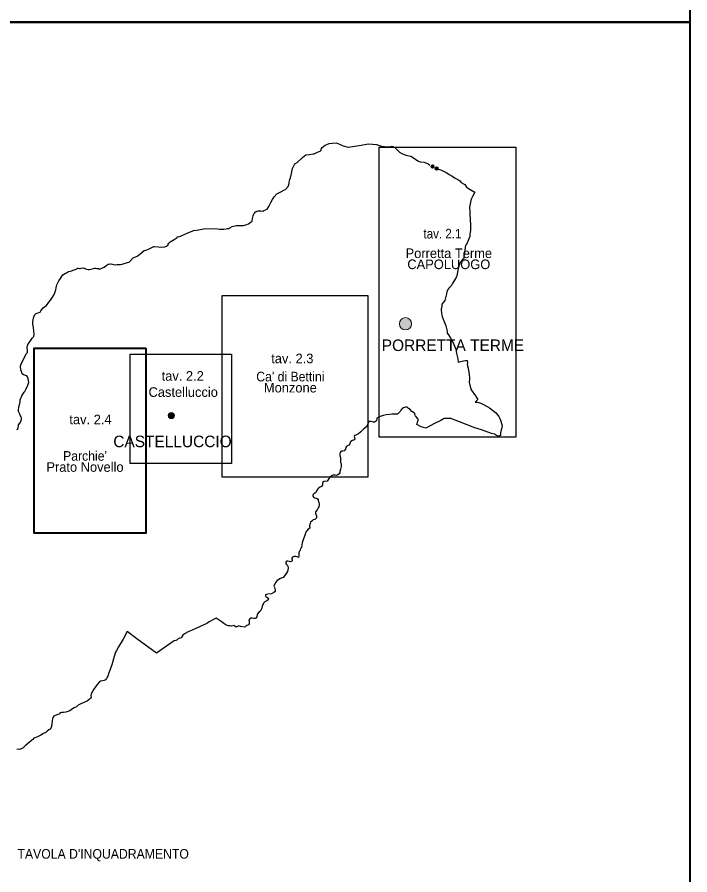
# Model space of a CAD drawing. Extents: x 650071 to 653841, y 889105 to 891996.
# Drawn here: x 650422 to 651121, y 889623 to 890515 of the extents above; entities that cross this region are included whole.
import ezdxf
from ezdxf.enums import TextEntityAlignment as Align

# ---------------------------------------------------------------- set-up
doc = ezdxf.new("R2010")
doc.units = 0
doc.header["$LTSCALE"] = 5.6
doc.header["$PDMODE"] = 32
doc.header["$PDSIZE"] = 2.8
doc.layers.add('61', color=7, linetype='Continuous', lineweight=35)

msp = doc.modelspace()

# ---------------------------------------------------------------- hatches: boundary and pattern name
at = {"layer": '61'}
for points in [[(650832.21, 890195.85, 1), (650819.49, 890195.85, 1)], [(650585.6, 890100.36, 1), (650579.24, 890100.36, 1)]]:
    msp.add_hatch(color=256, dxfattribs=at).paths.add_polyline_path(points)

# ---------------------------------------------------------------- linework, layer by layer
at = {"layer": '61', "lineweight": 40}
for p, q in [((650071.44, 890509.41), (651121.44, 890509.41)), ((651121.44, 890509.41), (651121.44, 889106.05))]:
    msp.add_line(p, q, dxfattribs=at)
for points in [[(651121.44, 891995.65), (651121.44, 890509.4), (650071.44, 890509.4), (650071.44, 891995.65)], [(650555.91, 890170.4), (650555.91, 889977.97), (650439.81, 889977.97), (650439.81, 890170.4)]]:
    msp.add_lwpolyline(points, close=True, dxfattribs=at)
at = {"layer": '61', "lineweight": 25}
for points in [[(650703.73, 890338.52), (650704.95, 890341.6), (650704.71, 890343.23), (650705.73, 890345.71), (650706.25, 890347.72), (650707.39, 890352.16), (650707.99, 890355.64), (650707.99, 890356.68), (650709.37, 890359.23), (650710.85, 890362), (650713.27, 890363.56), (650718.57, 890368.59), (650720.35, 890370.19), (650722.21, 890371.35), (650726.01, 890371.8), (650729.77, 890372.4), (650730.95, 890372.63), (650734.33, 890374.35), (650737.65, 890375.79), (650738.47, 890377.96), (650739.25, 890379.07), (650740.75, 890380.35), (650742.23, 890381.51), (650744.07, 890382.4), (650746.57, 890383.28), (650749.91, 890383.63), (650753.89, 890383.92), (650757.33, 890382.48), (650759.23, 890381.63), (650760.99, 890380.91), (650766.13, 890379.51), (650777.53, 890381.2), (650787.49, 890382.84), (650795.51, 890382.39), (650800.81, 890380.44), (650804.15, 890380.19), (650808.97, 890379.83), (650811.61, 890380.39), (650812.57, 890380.32), (650813.47, 890379.92)], [(650813.47, 890379.92), (650814.37, 890379.31), (650815.69, 890378.07), (650817.93, 890375.96), (650819.65, 890374.27), (650821.93, 890372.79), (650826.13, 890371.08), (650831.53, 890369.96), (650835.13, 890367.55), (650838.67, 890365.39), (650841.13, 890364.24), (650845.39, 890363.95), (650849.47, 890362.04), (650851.11, 890360.87)], [(650858.21, 890357.36), (650863.15, 890355.56), (650866.75, 890353.67), (650868.85, 890352.64), (650871.25, 890351.2), (650874.07, 890349.59), (650876.77, 890347.72), (650880.31, 890345.88), (650882.23, 890344.44), (650883.77, 890342.75), (650886.25, 890341.24), (650887.63, 890340.48), (650888.17, 890339.64), (650889.33, 890337.96), (650889.85, 890337.44), (650891.43, 890336.43), (650897.89, 890332.68), (650895.31, 890328), (650894.47, 890326.15), (650893.77, 890324.04), (650892.49, 890317.08), (650892.55, 890312.08), (650892.87, 890309.64), (650893.03, 890304.52), (650893.19, 890302.64), (650893.41, 890300.23), (650893.39, 890293.12), (650892.97, 890290.71), (650892.81, 890289.47), (650892.75, 890288.07), (650892.55, 890286.31), (650892.39, 890285.79), (650890.81, 890282.28), (650888.73, 890277.6), (650888.31, 890277.52), (650887.57, 890272.24), (650887.27, 890270.67), (650887.07, 890268.39), (650886.63, 890266.15), (650886.31, 890264.16)], [(650605.45, 890292.75), (650608.37, 890293.27), (650618.07, 890294.8), (650630.45, 890294.43), (650632.49, 890294.28), (650636.89, 890294.07), (650639.39, 890294.52), (650640.87, 890294.92), (650642.19, 890294.99), (650643.01, 890295.68), (650645.77, 890296.95), (650648.37, 890297.8), (650649.73, 890298.04), (650652.25, 890298.11), (650655.57, 890298.11), (650657.41, 890298.11), (650660.93, 890299.12), (650662.71, 890299.6), (650664.31, 890301), (650666.29, 890302.48), (650666.65, 890305.24), (650667.31, 890308.2), (650668.25, 890310.04), (650669.05, 890311.11), (650669.71, 890312.32), (650672.61, 890313.36), (650675.47, 890313.12), (650677.55, 890313.07), (650678.69, 890313.64), (650682.13, 890314.96), (650683.63, 890317.75), (650685.77, 890321.79), (650687.37, 890324.95), (650689.39, 890327.79), (650691.89, 890330.84), (650692.67, 890331.4), (650696.11, 890333.04), (650699.27, 890334.72), (650700.93, 890335.47), (650703.73, 890338.52)], [(650507.65, 890252.71), (650510.23, 890253.71), (650512.59, 890254.75), (650514.57, 890256.31), (650516.61, 890257.84), (650517.49, 890257.92), (650519.23, 890258.2), (650519.87, 890258.16), (650523.81, 890257.04), (650524.45, 890257.04), (650526.19, 890257.31), (650529.49, 890257.55), (650531.23, 890257.92), (650533.27, 890258.47), (650536.83, 890259.47), (650538.61, 890260), (650542.81, 890264.23), (650546.71, 890266.2), (650549.77, 890268.36), (650554.03, 890271.96), (650556.85, 890272.84), (650560.03, 890274.19), (650564.29, 890276.04), (650564.99, 890276.08), (650568.81, 890275.92), (650572.07, 890275.36), (650575.51, 890275.67), (650577.49, 890276.59), (650579.15, 890277.96), (650579.09, 890278.44), (650579.85, 890279.56), (650581.01, 890280.99), (650585.21, 890283.4), (650588.29, 890285.56), (650588.51, 890286.11), (650591.23, 890286.47), (650592.73, 890287.24), (650598.97, 890289.96), (650604.63, 890292.47), (650605.45, 890292.75)], [(650886.31, 890264.16), (650886.11, 890263.47), (650885.17, 890262.48), (650884.17, 890261.4), (650883.53, 890260.52), (650882.79, 890259.47), (650881.79, 890257.16), (650881.25, 890255.8), (650880.55, 890252.87), (650879.87, 890249.43), (650879.13, 890245.75), (650878.87, 890244.95), (650878.33, 890244.04), (650876.07, 890240.03), (650874.49, 890237.31), (650873.13, 890235.32), (650871.03, 890232.79), (650870.13, 890231.67), (650869.11, 890230.44), (650868.35, 890227.03), (650867.33, 890222.68), (650866.69, 890220.07), (650865.17, 890218.23), (650863.75, 890216.31), (650863.75, 890215.92), (650863.69, 890214.24), (650863.13, 890212.15), (650862.87, 890211.16), (650862.99, 890210.23), (650863.25, 890206.83), (650863.51, 890204.91), (650864.01, 890203.48), (650864.97, 890200.76), (650866.57, 890196.36), (650867.71, 890193.59), (650869.25, 890188.07), (650869.25, 890187.31), (650868.99, 890186.07), (650870.41, 890184.28), (650872.19, 890181.55)], [(650458.87, 890223.52), (650460.49, 890226.31), (650461.25, 890228.04), (650462.13, 890230.95), (650462.71, 890233.2), (650463.47, 890236.16), (650464.41, 890238.47), (650465.51, 890240.44), (650467.03, 890243.04), (650468.11, 890244.6), (650469.67, 890246.83), (650472.33, 890248.44), (650473.49, 890248.68), (650474.51, 890249.31), (650475.53, 890250.04), (650477.59, 890250.67), (650482.37, 890252.16), (650483.59, 890252.52), (650484.09, 890252.88), (650484.91, 890253.52), (650485.57, 890253.52), (650486.75, 890253.27), (650487.45, 890253.27), (650488.73, 890253.71), (650490.85, 890253.84), (650491.81, 890253.52), (650492.95, 890253.03), (650494.55, 890252.52), (650495.77, 890252.28), (650496.85, 890252.28), (650498.51, 890252.64), (650499.91, 890253.03), (650501.45, 890253.4), (650502.65, 890253.47), (650503.43, 890253.47), (650505.01, 890253.27), (650506.49, 890253.15), (650507.65, 890252.71)], [(650433.67, 890138.67), (650432.65, 890140.47), (650432.03, 890141.52), (650428.83, 890142.75), (650427.31, 890143.6), (650426.65, 890146.28), (650426.03, 890147.95), (650425.69, 890151.28), (650425.95, 890153.28), (650426.35, 890154.15), (650431.77, 890164.8), (650432.73, 890166.04), (650432.77, 890166.87), (650432.65, 890168.11), (650432.33, 890171.03), (650432.91, 890173.2), (650433.49, 890174.92), (650435.21, 890177.2), (650437.69, 890180.68), (650439.29, 890182.6), (650439.67, 890184.96), (650439.43, 890188.36), (650439.17, 890191.84), (650438.47, 890195.36), (650438.39, 890197.48), (650438.77, 890200.08), (650439.49, 890203.12), (650440.51, 890205.55), (650441.01, 890205.99), (650442.43, 890206.72), (650445.03, 890207.52), (650445.85, 890208.03), (650446.81, 890209.2), (650447.89, 890210.8), (650449.11, 890212.43), (650450.65, 890213.48), (650452.43, 890214.91), (650454.85, 890218.12), (650456.59, 890220.36), (650458.87, 890223.52)], [(650872.19, 890181.55), (650875.11, 890176.84), (650876.13, 890174.19), (650877.99, 890169.48), (650879.01, 890164.79), (650880.15, 890159.51), (650880.73, 890155.84), (650881.87, 890156.2), (650886.01, 890157.2), (650888.07, 890157.59), (650889.85, 890157.47), (650890.29, 890155.28), (650890.11, 890154.36), (650889.97, 890153.8), (650890.43, 890152.12), (650890.99, 890149.6), (650891.45, 890147.36), (650891.71, 890145.39), (650891.95, 890142.91), (650892.21, 890139.51), (650892.41, 890138.52), (650892.09, 890134.6), (650892.27, 890133.28), (650892.73, 890132.55), (650892.67, 890131.99), (650894.25, 890127.04), (650898.67, 890120.72), (650900.89, 890117.03), (650898.25, 890114.28), (650899.67, 890114.23), (650900.67, 890114.32), (650902.03, 890114), (650904.07, 890113.31), (650906.33, 890112.28), (650910.67, 890109.87), (650913.27, 890108.24), (650916.41, 890106.08), (650919.33, 890103.48), (650921.31, 890101.16), (650922.97, 890099.24)], [(650421.81, 890085.72), (650422.69, 890086.15), (650422.83, 890086.96), (650423.21, 890087.95), (650423.35, 890089.44), (650423.59, 890090.8), (650424.81, 890092.52), (650426.23, 890094.83), (650426.53, 890096.51), (650426.53, 890097.72), (650426.23, 890099.08), (650425.71, 890100.08), (650424.81, 890101.96), (650423.53, 890104.75), (650423.41, 890105.87), (650423.91, 890109.47), (650424.87, 890112.92), (650425.33, 890114.6), (650425.27, 890116.59), (650426.91, 890120.8), (650428.07, 890122.67), (650429.35, 890124.59), (650430.11, 890125.24), (650431.39, 890128.11), (650433.05, 890132), (650434.27, 890134.68), (650433.67, 890138.67)], [(650822.67, 890108.2), (650820.97, 890105.88), (650820.43, 890104.56), (650819.29, 890103.52), (650817.51, 890101.92), (650816.49, 890101.87), (650813.25, 890101.95), (650812.09, 890101.87), (650809.31, 890101.48), (650805.71, 890101.2), (650802.43, 890100.55), (650799.45, 890099.36), (650796.05, 890097.6), (650795.65, 890094.96), (650793.47, 890093.36), (650792.53, 890093.56), (650790.01, 890094.11), (650787.61, 890094.16), (650786.75, 890091.79), (650785.11, 890088.68), (650782.19, 890086.24), (650779.47, 890083.56), (650776.95, 890081.24), (650774.29, 890080.12), (650772.63, 890079.55), (650772.37, 890078.51), (650772.85, 890077.71), (650773.17, 890076.12), (650772.57, 890075.07), (650770.67, 890074.28), (650768.89, 890073.48), (650768.41, 890072.56), (650768.01, 890070.79), (650766.77, 890069.68), (650765.25, 890068.79), (650764.39, 890068.12), (650763.85, 890067.23), (650763.55, 890065.36), (650762.87, 890064.28), (650762.13, 890063.63)], [(650922.97, 890099.24), (650923.87, 890097.27), (650924.89, 890094.6), (650926.15, 890089.76), (650926.03, 890087.71), (650925.41, 890085.35), (650924.73, 890082.28), (650924.45, 890079.47), (650922.43, 890078.88), (650920.51, 890079.52), (650918.21, 890080.99), (650915.15, 890081.76), (650912.43, 890082.84), (650910.25, 890083.48), (650907.47, 890084.6), (650904.67, 890085.35), (650897.89, 890087.52), (650889.99, 890090.55), (650882.11, 890094), (650872.99, 890097.24), (650865.91, 890097.36), (650862.39, 890095.39), (650856.13, 890092.11), (650847.03, 890087.4), (650842.15, 890088.75), (650837.59, 890091), (650838.69, 890094.4), (650839.37, 890095.87), (650837.95, 890097.96), (650836.31, 890099.95), (650835.49, 890101.4), (650835.49, 890102.72), (650835.15, 890102.87), (650832.57, 890104.44), (650830.61, 890106.55), (650828.97, 890107.87), (650827.61, 890108.92), (650826.25, 890109.12), (650824.79, 890108.87), (650822.67, 890108.2)], [(650762.13, 890063.63), (650760.73, 890063.24), (650759.21, 890063.2), (650758.53, 890063), (650757.79, 890061.92), (650757.41, 890060.68), (650757.69, 890058.88), (650758.15, 890056.91), (650758.21, 890055.32), (650758.21, 890053.24), (650758.35, 890052), (650758.69, 890050.96), (650758.99, 890049.99), (650758.99, 890048.71), (650758.83, 890047.28), (650758.25, 890044.44), (650757.61, 890042.28), (650757.67, 890040.84), (650756.99, 890039.91), (650755.41, 890038.76), (650753.95, 890038.07), (650752.83, 890038.2), (650750.49, 890038.2), (650749.67, 890037.87), (650747.61, 890036.27), (650746.39, 890035.16), (650744.35, 890032.24), (650741.13, 890031.87), (650739.61, 890030.59), (650739.57, 890028.27), (650738.65, 890026.67), (650737.03, 890025.8), (650735.53, 890024.95), (650734.65, 890024.19), (650733.59, 890022.39), (650732.31, 890020.12), (650731.49, 890019.64), (650730.41, 890018.92), (650729.83, 890018.19), (650729.59, 890017.32)], [(650729.59, 890017.32), (650729.63, 890016.43), (650730.37, 890015.2), (650731.19, 890014.92), (650733.25, 890014.35), (650734.99, 890013.55), (650735.19, 890011.99), (650735.23, 890011.03), (650735.77, 890009.87), (650736.07, 890008.72), (650736.07, 890007.83), (650735.73, 890005.6), (650735.09, 890004.23), (650733.87, 890002.43), (650732.75, 890000.64), (650732.35, 889999.44), (650732.41, 889998.27), (650732.81, 889997.2), (650733.41, 889996.19), (650733.21, 889994.08), (650732.33, 889992.87), (650731.51, 889992.39), (650729.71, 889991.76), (650728.33, 889990.68), (650727.21, 889989.51), (650726.53, 889988.28), (650726.09, 889985.71), (650726.19, 889983.16), (650724.77, 889982.16), (650723.31, 889980.56), (650722.53, 889979.63), (650721.11, 889975.96), (650719.15, 889970.24), (650718.43, 889968.39), (650718.05, 889965.71), (650717.55, 889963.28), (650716.69, 889962), (650716.43, 889960.72), (650716.15, 889959.92), (650715.13, 889958.88)], [(650715.13, 889958.88), (650714.87, 889957.36), (650714.97, 889956.04), (650714.97, 889954.68), (650714.47, 889952.72), (650713.35, 889953.28), (650711.71, 889953.68), (650709.99, 889953.72), (650709.01, 889953.59), (650708.23, 889952.96), (650707.75, 889952.16), (650707.69, 889951.36), (650707.95, 889950.27), (650707.95, 889949.28), (650707.21, 889948.43), (650705.85, 889948.24), (650705.11, 889948.48), (650703.61, 889948.99), (650702.39, 889948.95), (650701.69, 889948.48), (650701.31, 889947.52), (650701.51, 889946.64), (650702.15, 889945.59), (650703.21, 889944.36), (650703.51, 889943.71), (650703.91, 889941.63), (650703.13, 889938.32), (650700.97, 889935.2), (650698.53, 889932.07), (650695.81, 889930.75), (650694.13, 889929.8), (650692.29, 889928.87), (650690.63, 889926.59), (650689.07, 889923.08), (650689.85, 889920.83), (650690.15, 889918.72), (650690.15, 889917.31), (650688.97, 889916.28), (650686.45, 889915.04), (650682.73, 889914.48)], [(650682.73, 889914.48), (650681.17, 889914.39), (650680.29, 889914), (650680.09, 889913.04), (650680.49, 889912.2), (650682.73, 889910.68), (650683.41, 889909.92), (650683.13, 889908.71), (650681.77, 889907.84), (650679.51, 889906.72), (650678.05, 889905.11), (650677.09, 889902.88), (650676.03, 889899.2), (650674.57, 889896.47), (650673.01, 889895.52), (650671.75, 889893.63), (650671.15, 889890.96), (650670.37, 889889.64), (650669.41, 889889.27), (650668.23, 889889.44), (650666.29, 889889.75), (650665.11, 889889.55), (650663.95, 889888.88), (650662.97, 889887.56), (650663.35, 889885.68), (650663.45, 889883.79), (650662.57, 889882.72), (650660.91, 889882.16), (650660.41, 889881.88), (650658.77, 889880.19), (650654.17, 889880.92), (650652.53, 889881.71), (650649.65, 889880.36), (650647.21, 889882.16), (650644.97, 889881.31), (650643.41, 889881.71), (650641.45, 889881.6), (650638.93, 889882.72), (650636.97, 889884.16), (650634.23, 889886.32)], [(650634.23, 889886.32), (650631.21, 889888.23), (650628.97, 889889.55), (650626.93, 889888.51), (650621.65, 889885.68), (650619.41, 889884.24), (650611.69, 889880.56), (650603.89, 889877.16), (650600.59, 889875.84), (650595.91, 889873.27), (650594.15, 889871.87), (650592.71, 889869.28), (650591.35, 889868.76), (650589.41, 889868.16), (650588.33, 889867.19), (650586.97, 889866.52), (650585.33, 889866.04), (650584.11, 889865.32), (650566.77, 889853.4), (650546.59, 889868.08), (650536.29, 889875.76), (650532.29, 889867.76), (650527.59, 889859.92), (650525.23, 889856.04), (650524.47, 889854.39), (650522.83, 889849.63), (650520.39, 889841), (650519.51, 889838.23), (650518.81, 889836.12), (650517.53, 889832.64), (650516.25, 889829.43), (650514.91, 889826.88), (650513.77, 889825.4), (650512.69, 889824.88), (650511.11, 889824.64), (650508.87, 889824.07), (650507.71, 889823.28), (650505.09, 889820.6), (650501.83, 889815.88), (650499.15, 889810.8)], [(650499.15, 889810.8), (650498.83, 889809.03), (650498.89, 889807.55), (650498.47, 889806.52), (650496.99, 889805.11), (650494.69, 889803.51), (650491.37, 889801.83), (650487.73, 889800.11), (650485.51, 889799.07), (650483.65, 889797.39), (650481.37, 889796.32), (650479.69, 889795.4), (650476.69, 889793.24), (650474.65, 889792.44), (650472.81, 889791.83), (650470.13, 889791.44), (650468.21, 889791.44), (650466.93, 889791.07), (650465.83, 889789.96), (650464.19, 889789.4), (650461.45, 889788.4), (650460.23, 889787.72), (650459.21, 889786.19), (650458.87, 889785), (650458.51, 889782.8), (650457.69, 889776.92), (650457.25, 889775.31), (650456.41, 889774.2), (650455.01, 889773.39), (650453.41, 889772.2), (650451.81, 889770.91), (650449.51, 889769.6), (650446.83, 889767.95), (650443.13, 889766.32), (650439.55, 889764.72), (650438.29, 889763.47), (650436.61, 889762.04), (650434.95, 889760.68), (650432.97, 889758.88), (650430.43, 889756.79)], [(650430.43, 889756.79), (650428.21, 889754.88), (650424.89, 889753.2), (650424.31, 889753.27), (650421.89, 889753.2)]]:
    msp.add_lwpolyline(points, dxfattribs=at)
for points in [[(650798.39, 890379.4), (650940.47, 890379.4), (650940.47, 890077.87), (650798.39, 890077.87)], [(650635.21, 890225.33), (650786.53, 890225.33), (650786.53, 890036.3), (650635.21, 890036.3)], [(650539.49, 890164.31), (650645.01, 890164.31), (650645.01, 890050.46), (650539.49, 890050.46)]]:
    msp.add_lwpolyline(points, close=True, dxfattribs=at)
at = {"layer": '61', "lineweight": 13}
for centre, radius in [((650825.85, 890195.85), 6.36), ((650582.42, 890100.36), 3.18)]:
    msp.add_circle(centre, radius, dxfattribs=at)
at = {"layer": '61'}
for p in [(650854.03, 890359.36), (650858.21, 890357.36)]:
    msp.add_point(p, dxfattribs=at)

# ---------------------------------------------------------------- texts
for s, width, p in [('tav. 2.1', 0.9, (650844.49, 890284.53)), ("TAVOLA D'INQUADRAMENTO", 0.95, (650422.41, 889639.56))]:
    msp.add_text(s, height=10, dxfattribs=dict(at, width=width)).set_placement(p)
for s, height, p in [('Porretta Terme', 10, (650870.86, 890264.15)), ('CAPOLUOGO', 10, (650870.85, 890252.65)), ('PORRETTA TERME', 12, (650875.15, 890167.48)), ('Monzone', 10, (650706.12, 890124.39)), ('Castelluccio', 10, (650594.71, 890119.77)), ('CASTELLUCCIO', 12, (650583.56, 890067.47)), ('Prato Novello', 10, (650492.57, 890041.87))]:
    msp.add_text(s, height=height, dxfattribs=at).set_placement(p, align=Align.CENTER)
for s, p in [('tav. 2.3', (650686.23, 890154.76)), ('tav. 2.2', (650572.29, 890136.58)), ('tav. 2.4', (650476.36, 890091.33))]:
    msp.add_text(s, height=10, dxfattribs=at).set_placement(p)
at = {"layer": '61', "width": 0.95}
for s, p in [("Ca' di Bettini", (650706.12, 890135.89)), ("Parchie'", (650492.57, 890053.37))]:
    msp.add_text(s, height=10, dxfattribs=at).set_placement(p, align=Align.CENTER)

doc.saveas('drawing.dxf')
